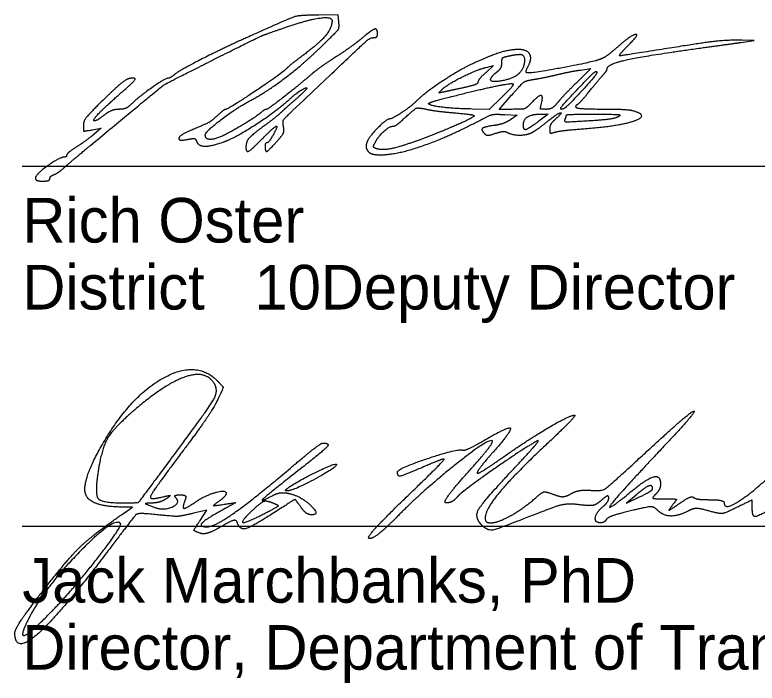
# Model space of a CAD drawing. Extents: x 0 to 34, y 0 to 22.
# Drawn here: x 24.977 to 27.305, y 5.404 to 7.5 of the extents above; entities that cross this region are included whole.
import ezdxf

# ---------------------------------------------------------------- set-up
doc = ezdxf.new("R2010")
doc.units = 0
doc.layers.add('SH_Data', color=7, linetype='Continuous')
doc.layers.add('SH_Text', color=7, linetype='Continuous')

msp = doc.modelspace()

# ---------------------------------------------------------------- linework, layer by layer
at = {"layer": 'SH_Data'}
for p, q in [((25, 7.0256), (28.5, 7.0256)), ((25, 5.8962), (28.5, 5.8962))]:
    msp.add_line(p, q, dxfattribs=at)
at = {"layer": 'SH_Text'}
for p, q in [((25.0414, 6.9885), (25.0414, 6.9885)), ((25.4623, 6.1012), (25.4623, 6.1012)), ((25.8276, 6.0114), (25.8276, 6.0114)), ((26.9766, 6.0134), (26.9766, 6.0134)), ((25.7828, 5.9697), (25.7828, 5.9697)), ((26.1995, 5.9824), (26.1995, 5.9824))]:
    msp.add_line(p, q, dxfattribs=at)
for points in [[(25.9926, 7.4778), (25.9902, 7.4996), (25.9302, 7.4989)], [(27.2539, 7.4131), (27.2952, 7.4189), (27.2575, 7.4199)], [(26.4552, 7.335), (26.4777, 7.3403), (26.4533, 7.318)], [(26.7502, 7.3265), (26.7828, 7.3312), (26.739, 7.2879)], [(26.5037, 7.2413), (26.4645, 7.2033), (26.4111, 7.2043)], [(26.5364, 7.2033), (26.4955, 7.2033), (26.5347, 7.2479)], [(26.513, 7.1869), (26.5522, 7.1846), (26.5308, 7.1706)], [(26.624, 7.1883), (26.6491, 7.1883), (26.6196, 7.166)], [(25.2195, 7.1391), (25.2477, 7.1441), (25.2252, 7.1252)], [(26.9248, 5.9937), (26.8953, 5.9681), (26.936, 5.9878)], [(25.3146, 5.9343), (25.3453, 5.9555), (25.3075, 5.9562)], [(25.5576, 5.9144), (25.5788, 5.9468), (25.5371, 5.9367)]]:
    msp.add_lwpolyline(points, dxfattribs=at)
for points in [[(25.9302, 7.4989), (25.8677, 7.4982), (25.8413, 7.49), (25.7052, 7.4288)], [(25.8327, 7.4628), (25.8967, 7.4847), (25.9714, 7.4947), (25.9714, 7.4814)], [(25.9714, 7.4814), (25.9714, 7.4575), (25.9264, 7.4061), (25.8672, 7.3626)], [(25.9326, 7.3953), (25.9866, 7.4476), (25.9948, 7.4589), (25.9926, 7.4778)], [(25.6227, 7.3706), (25.7348, 7.4269), (25.7605, 7.4382), (25.8327, 7.4628)], [(26.1139, 7.4396), (26.1139, 7.4576), (26.0963, 7.4527), (26.0646, 7.4259)], [(25.7052, 7.4288), (25.625, 7.3928), (25.4891, 7.3232), (25.4758, 7.3114)], [(25.8476, 7.1992), (26.069, 7.4088), (26.0909, 7.4283), (26.1045, 7.4283)], [(26.1045, 7.4283), (26.1097, 7.4283), (26.1139, 7.4334), (26.1139, 7.4396)], [(26.9007, 7.404), (26.9375, 7.4408), (26.908, 7.4355), (26.8651, 7.3975)], [(26.0646, 7.4259), (26.0484, 7.4122), (26.0115, 7.3857), (25.9827, 7.3671)], [(26.9974, 7.39), (26.8771, 7.3705), (26.8684, 7.3717), (26.9007, 7.404)], [(27.2575, 7.4199), (27.213, 7.421), (27.1291, 7.4114), (26.9974, 7.39)], [(27.1272, 7.3955), (27.1742, 7.402), (27.2312, 7.4099), (27.2539, 7.4131)], [(25.7093, 7.2274), (25.763, 7.2558), (25.8777, 7.342), (25.9326, 7.3953)], [(26.5565, 7.3908), (26.529, 7.3908), (26.4672, 7.3717), (26.4117, 7.346)], [(26.5866, 7.3386), (26.5994, 7.3625), (26.5831, 7.3908), (26.5565, 7.3908)], [(26.8651, 7.3975), (26.8459, 7.3806), (26.8234, 7.3642), (26.8152, 7.3612)], [(26.8339, 7.3305), (26.8339, 7.3449), (26.9565, 7.3721), (27.1272, 7.3955)], [(25.2139, 7.0904), (25.4385, 7.2764), (25.4481, 7.2829), (25.6227, 7.3706)], [(25.8672, 7.3626), (25.8523, 7.3516), (25.8342, 7.3367), (25.8269, 7.3295)], [(25.9827, 7.3671), (25.9538, 7.3485), (25.92, 7.3245), (25.9077, 7.3139)], [(26.5039, 7.3491), (26.5039, 7.3625), (26.5092, 7.3675), (26.5273, 7.3711)], [(26.5273, 7.3711), (26.5402, 7.3737), (26.5554, 7.3758), (26.5611, 7.3758)], [(26.5611, 7.3758), (26.5761, 7.3758), (26.5741, 7.3331), (26.5583, 7.3164)], [(26.8152, 7.3612), (26.7878, 7.3511), (26.5861, 7.3137), (26.5818, 7.3179)], [(26.4117, 7.346), (26.3697, 7.3265), (26.2612, 7.2542), (26.2355, 7.2285)], [(26.3164, 7.2656), (26.3308, 7.2805), (26.4259, 7.328), (26.4552, 7.335)], [(26.4903, 7.3219), (26.4978, 7.3273), (26.5039, 7.3395), (26.5039, 7.3491)], [(26.5818, 7.3179), (26.5796, 7.3202), (26.5817, 7.3295), (26.5866, 7.3386)], [(25.4758, 7.3114), (25.4693, 7.3056), (25.4607, 7.3008), (25.4567, 7.3008)], [(25.8269, 7.3295), (25.8121, 7.3146), (25.6453, 7.2033), (25.638, 7.2033)], [(25.9077, 7.3139), (25.863, 7.2755), (25.7703, 7.2033), (25.7656, 7.2033)], [(26.4533, 7.318), (26.4399, 7.3058), (26.4289, 7.2924), (26.4289, 7.2882)], [(26.5583, 7.3164), (26.5419, 7.2991), (26.4609, 7.2857), (26.4706, 7.3019)], [(26.4706, 7.3019), (26.474, 7.3075), (26.4828, 7.3165), (26.4903, 7.3219)], [(26.6046, 7.2973), (26.6214, 7.2999), (26.6537, 7.3065), (26.6764, 7.3119)], [(26.6764, 7.3119), (26.6991, 7.3174), (26.7323, 7.3239), (26.7502, 7.3265)], [(26.8009, 7.3213), (26.8044, 7.3179), (26.7805, 7.2889), (26.7279, 7.2325)], [(26.7763, 7.3028), (26.7879, 7.3149), (26.799, 7.3233), (26.8009, 7.3213)], [(26.7814, 7.2633), (26.7999, 7.286), (26.8193, 7.309), (26.8245, 7.3145)], [(26.8245, 7.3145), (26.8297, 7.3199), (26.8339, 7.3271), (26.8339, 7.3305)], [(25.3343, 7.2995), (25.3262, 7.2982), (25.2908, 7.2688), (25.2555, 7.2342)], [(25.3245, 7.2679), (25.3522, 7.2921), (25.3556, 7.303), (25.3343, 7.2995)], [(25.4567, 7.3008), (25.448, 7.3008), (25.3583, 7.237), (25.3392, 7.2172)], [(26.4289, 7.2882), (26.4289, 7.2841), (26.4095, 7.2765), (26.3858, 7.2714)], [(26.5347, 7.2479), (26.5671, 7.2847), (26.5793, 7.2933), (26.6046, 7.2973)], [(26.739, 7.2879), (26.7149, 7.264), (26.6876, 7.2352), (26.6783, 7.2239)], [(26.6918, 7.2033), (26.6839, 7.2033), (26.7053, 7.2285), (26.7763, 7.3028)], [(25.2245, 7.1677), (25.2208, 7.1714), (25.2677, 7.2184), (25.3245, 7.2679)], [(25.8364, 7.2336), (25.8508, 7.2463), (25.869, 7.2602), (25.8767, 7.2645)], [(25.8767, 7.2645), (25.8975, 7.2761), (25.8849, 7.2583), (25.8523, 7.2301)], [(26.3239, 7.258), (26.3071, 7.2544), (26.3063, 7.2552), (26.3164, 7.2656)], [(26.3858, 7.2714), (26.3621, 7.2663), (26.3342, 7.2602), (26.3239, 7.258)], [(26.3292, 7.239), (26.426, 7.2638), (26.5355, 7.2867), (26.5393, 7.2829)], [(26.5393, 7.2829), (26.5413, 7.2809), (26.5253, 7.2622), (26.5037, 7.2413)], [(26.6283, 7.2221), (26.6345, 7.2468), (26.6185, 7.2468), (26.595, 7.222)], [(26.742, 7.2196), (26.7451, 7.221), (26.7628, 7.2406), (26.7814, 7.2633)], [(25.2555, 7.2342), (25.2091, 7.1888), (25.1914, 7.1662), (25.1914, 7.1528)], [(25.3392, 7.2172), (25.3319, 7.2096), (25.3156, 7.2033), (25.3031, 7.2033)], [(25.5739, 7.1234), (25.5739, 7.1329), (25.6697, 7.2065), (25.7093, 7.2274)], [(25.6272, 7.0996), (25.6642, 7.1124), (25.7908, 7.1934), (25.8364, 7.2336)], [(25.8523, 7.2301), (25.8377, 7.2174), (25.8201, 7.2016), (25.8132, 7.1949)], [(26.2355, 7.2285), (26.2202, 7.2132), (26.1609, 7.1733), (26.1534, 7.1733)], [(26.2743, 7.2204), (26.2723, 7.2224), (26.297, 7.2308), (26.3292, 7.239)], [(26.4111, 7.2043), (26.3558, 7.2052), (26.2806, 7.2141), (26.2743, 7.2204)], [(26.595, 7.222), (26.5804, 7.2066), (26.5702, 7.2033), (26.5364, 7.2033)], [(26.6426, 7.2033), (26.6261, 7.2033), (26.6242, 7.2058), (26.6283, 7.2221)], [(26.6783, 7.2239), (26.6681, 7.2114), (26.6541, 7.2033), (26.6426, 7.2033)], [(26.7279, 7.2325), (26.7129, 7.2165), (26.6967, 7.2033), (26.6918, 7.2033)], [(26.7364, 7.2102), (26.7364, 7.214), (26.7389, 7.2182), (26.742, 7.2196)], [(25.3031, 7.2033), (25.2901, 7.2033), (25.2693, 7.1949), (25.2544, 7.1835)], [(25.638, 7.2033), (25.6354, 7.2033), (25.6242, 7.1949), (25.613, 7.1846)], [(25.7517, 7.1957), (25.7371, 7.1834), (25.6893, 7.1529), (25.6525, 7.1324)], [(25.7656, 7.2033), (25.7629, 7.2033), (25.7567, 7.1999), (25.7517, 7.1957)], [(25.8132, 7.1949), (25.8063, 7.1881), (25.7818, 7.1687), (25.7588, 7.1517)], [(25.8191, 7.1496), (25.8162, 7.1649), (25.8219, 7.1749), (25.8476, 7.1992)], [(26.1856, 7.1641), (26.2298, 7.2043), (26.2407, 7.2094), (26.2695, 7.2032)], [(26.2695, 7.2032), (26.285, 7.1999), (26.3258, 7.1948), (26.3602, 7.1919)], [(26.817, 7.2032), (26.7727, 7.2033), (26.7364, 7.2064), (26.7364, 7.2102)], [(26.7664, 7.143), (26.8777, 7.1516), (26.9663, 7.1847), (26.9148, 7.1985)], [(26.9148, 7.1985), (26.9054, 7.2011), (26.8614, 7.2032), (26.817, 7.2032)], [(25.2544, 7.1835), (25.2402, 7.1727), (25.2267, 7.1655), (25.2245, 7.1677)], [(25.613, 7.1846), (25.5938, 7.1668), (25.5794, 7.1588), (25.5233, 7.135)], [(26.1534, 7.1733), (26.1425, 7.1733), (26.0854, 7.1149), (26.0801, 7.0983)], [(26.4164, 7.1813), (26.407, 7.1732), (26.305, 7.1294), (26.2414, 7.106)], [(26.3602, 7.1919), (26.3946, 7.189), (26.4199, 7.1842), (26.4164, 7.1813)], [(26.4307, 7.1667), (26.4656, 7.1849), (26.4812, 7.1887), (26.513, 7.1869)], [(26.5308, 7.1706), (26.519, 7.1629), (26.4962, 7.1549), (26.4802, 7.1527)], [(26.5714, 7.1534), (26.5714, 7.1708), (26.5978, 7.1883), (26.624, 7.1883)], [(26.6449, 7.1639), (26.6775, 7.1903), (26.6968, 7.1948), (26.669, 7.1696)], [(26.7767, 7.1668), (26.7131, 7.1628), (26.6994, 7.1638), (26.7025, 7.172)], [(26.7025, 7.172), (26.7047, 7.1775), (26.7064, 7.1835), (26.7064, 7.1852)], [(26.7064, 7.1852), (26.7064, 7.1869), (26.7461, 7.1882), (26.7945, 7.1881)], [(26.8686, 7.1797), (26.8609, 7.1753), (26.8195, 7.1694), (26.7767, 7.1668)], [(26.7945, 7.1881), (26.8616, 7.1879), (26.8793, 7.1859), (26.8686, 7.1797)], [(25.1914, 7.1528), (25.1914, 7.1354), (25.1932, 7.1345), (25.2195, 7.1391)], [(25.7588, 7.1517), (25.7189, 7.1222), (25.7014, 7.1015), (25.7014, 7.0838)], [(25.7513, 7.1096), (25.7897, 7.1485), (25.8038, 7.1532), (25.7854, 7.1209)], [(25.7988, 7.1031), (25.8165, 7.1232), (25.8218, 7.1354), (25.8191, 7.1496)], [(26.1074, 7.1008), (26.1171, 7.1195), (26.1514, 7.1502), (26.1631, 7.1506)], [(26.1245, 7.0608), (26.1741, 7.0608), (26.3334, 7.1159), (26.4307, 7.1667)], [(26.1631, 7.1506), (26.1675, 7.1507), (26.1776, 7.1568), (26.1856, 7.1641)], [(26.4802, 7.1527), (26.4487, 7.1485), (26.4377, 7.1391), (26.4499, 7.1269)], [(26.6196, 7.166), (26.5876, 7.1418), (26.5714, 7.1376), (26.5714, 7.1534)], [(26.5977, 7.1302), (26.6059, 7.1344), (26.6272, 7.1496), (26.6449, 7.1639)], [(26.669, 7.1696), (26.6607, 7.1621), (26.6539, 7.1494), (26.6539, 7.1413)], [(25.2252, 7.1252), (25.2128, 7.1149), (25.1883, 7.0972), (25.1708, 7.0859)], [(25.5233, 7.135), (25.492, 7.1218), (25.4899, 7.1027), (25.5205, 7.1094)], [(25.6525, 7.1324), (25.6154, 7.1117), (25.5739, 7.1069), (25.5739, 7.1234)], [(26.4499, 7.1269), (26.4551, 7.1217), (26.4661, 7.122), (26.4843, 7.1281)], [(26.4843, 7.1281), (26.4991, 7.1329), (26.515, 7.1345), (26.5198, 7.1316)], [(26.5198, 7.1316), (26.5338, 7.1229), (26.5815, 7.1221), (26.5977, 7.1302)], [(26.6539, 7.1413), (26.6539, 7.1295), (26.6573, 7.1276), (26.6708, 7.1318)], [(26.6708, 7.1318), (26.6801, 7.1346), (26.7231, 7.1397), (26.7664, 7.143)], [(25.5205, 7.1094), (25.5361, 7.1128), (25.5432, 7.1109), (25.5465, 7.1025)], [(25.5465, 7.1025), (25.5519, 7.0884), (25.5906, 7.087), (25.6272, 7.0996)], [(25.7014, 7.0838), (25.7014, 7.0677), (25.7189, 7.0767), (25.7513, 7.1096)], [(25.7614, 7.0871), (25.7614, 7.0689), (25.7732, 7.074), (25.7988, 7.1031)], [(25.7854, 7.1209), (25.7784, 7.1085), (25.7701, 7.0984), (25.767, 7.0984)], [(26.1083, 7.0807), (26.1012, 7.0836), (26.101, 7.0884), (26.1074, 7.1008)], [(26.2414, 7.106), (26.1841, 7.085), (26.1251, 7.0738), (26.1083, 7.0807)], [(25.1314, 7.0206), (25.1417, 7.0299), (25.1788, 7.0613), (25.2139, 7.0904)], [(25.1708, 7.0859), (25.1532, 7.0746), (25.1389, 7.0626), (25.1389, 7.0593)], [(25.767, 7.0984), (25.7639, 7.0984), (25.7614, 7.0933), (25.7614, 7.0871)], [(26.0801, 7.0983), (26.0774, 7.0896), (26.0792, 7.0777), (26.0842, 7.0717)], [(25.1389, 7.0593), (25.1389, 7.056), (25.1355, 7.0533), (25.1313, 7.0533)], [(26.0842, 7.0717), (26.0895, 7.0654), (26.1063, 7.0608), (26.1245, 7.0608)], [(25.1313, 7.0533), (25.1171, 7.0533), (25.0414, 6.9988), (25.0414, 6.9885)], [(25.0995, 6.9987), (25.1067, 7.0014), (25.1211, 7.0112), (25.1314, 7.0206)], [(25.0414, 6.9885), (25.0414, 6.9822), (25.0499, 6.9783), (25.0639, 6.9783)], [(25.0639, 6.9783), (25.0763, 6.9783), (25.0864, 6.9818), (25.0864, 6.9861)], [(25.0864, 6.9861), (25.0864, 6.9903), (25.0923, 6.996), (25.0995, 6.9987)], [(25.251, 6.152), (25.3372, 6.3024), (25.5454, 6.4184), (25.611, 6.3527)], [(25.6021, 6.3436), (25.5761, 6.3856), (25.45, 6.3444), (25.3547, 6.2628)], [(25.4623, 6.1012), (25.5837, 6.2647), (25.6161, 6.3209), (25.6021, 6.3436)], [(25.611, 6.3527), (25.6298, 6.334), (25.6298, 6.3289), (25.6115, 6.2905)], [(25.6115, 6.2905), (25.6006, 6.2675), (25.5488, 6.192), (25.4966, 6.1226)], [(25.3547, 6.2628), (25.288, 6.2058), (25.2492, 6.1416), (25.2381, 6.0704)], [(26.5047, 6.1105), (26.5853, 6.1671), (26.7166, 6.2443), (26.7323, 6.2443)], [(26.7323, 6.2443), (26.7372, 6.2443), (26.6959, 6.2017), (26.6405, 6.1496)], [(26.959, 6.1309), (27.034, 6.2), (27.1, 6.2566), (27.1058, 6.2567)], [(27.1058, 6.2567), (27.1115, 6.2568), (27.0595, 6.1966), (26.9901, 6.123)], [(26.4458, 6.164), (26.5245, 6.2101), (26.5368, 6.1969), (26.4775, 6.1296)], [(25.3075, 5.9562), (25.2096, 5.9579), (25.1862, 6.039), (25.251, 6.152)], [(25.8411, 6.0785), (25.8916, 6.1214), (25.9371, 6.1565), (25.9422, 6.1566)], [(25.9422, 6.1566), (25.9671, 6.1571), (25.9437, 6.1316), (25.8578, 6.0643)], [(26.4738, 6.1637), (26.4642, 6.1734), (26.2545, 6.0064), (26.1766, 5.9271)], [(26.6141, 6.1633), (26.565, 6.1355), (26.3767, 6.0033), (26.3635, 5.9873)], [(26.3801, 6.1348), (26.3857, 6.1329), (26.4152, 6.1461), (26.4458, 6.164)], [(26.396, 6.0634), (26.4423, 6.1151), (26.4773, 6.1603), (26.4738, 6.1637)], [(26.6405, 6.1496), (26.5409, 6.0559), (26.4516, 5.9477), (26.4516, 5.9208)], [(26.5489, 6.0844), (26.5951, 6.1336), (26.6244, 6.1691), (26.6141, 6.1633)], [(26.1768, 6.0662), (26.177, 6.0767), (26.3644, 6.1399), (26.3801, 6.1348)], [(26.4775, 6.1296), (26.4495, 6.0978), (26.4266, 6.0681), (26.4266, 6.0637)], [(26.784, 6.0085), (26.8175, 6.0057), (26.8409, 6.0221), (26.959, 6.1309)], [(26.9901, 6.123), (26.8606, 5.9855), (26.8285, 5.9382), (26.9107, 6.0059)], [(25.3162, 5.9693), (25.3628, 5.9693), (25.3674, 5.9734), (25.4623, 6.1012)], [(25.4966, 6.1226), (25.4443, 6.0532), (25.4016, 5.9926), (25.4016, 5.9878)], [(26.1995, 5.9824), (26.2705, 6.0508), (26.3258, 6.1068), (26.3224, 6.1068)], [(26.3224, 6.1068), (26.319, 6.1068), (26.2899, 6.0956), (26.2578, 6.0818)], [(26.4266, 6.0637), (26.4266, 6.0592), (26.4617, 6.0803), (26.5047, 6.1105)], [(25.5797, 5.8943), (25.6028, 5.8943), (25.7289, 5.9831), (25.8411, 6.0785)], [(25.8276, 6.0114), (25.848, 6.0292), (25.9801, 6.095), (25.9852, 6.0899)], [(25.9852, 6.0899), (25.9914, 6.0837), (25.8488, 6.0068), (25.8311, 6.0068)], [(26.2578, 6.0818), (26.1952, 6.055), (26.1765, 6.0514), (26.1768, 6.0662)], [(26.4418, 5.8987), (26.4166, 5.9239), (26.4455, 5.974), (26.5489, 6.0844)], [(25.2381, 6.0704), (25.2267, 5.997), (25.2481, 5.9693), (25.3162, 5.9693)], [(25.8578, 6.0643), (25.7646, 5.9913), (25.7432, 5.9697), (25.7871, 5.9932)], [(26.3302, 5.9693), (26.3199, 5.9693), (26.3488, 6.0106), (26.396, 6.0634)], [(27.2016, 5.9678), (27.2016, 5.945), (27.2969, 6.0064), (27.3672, 6.0746)], [(26.9107, 6.0059), (26.9591, 6.0458), (27.0016, 6.0562), (27.0016, 6.0281)], [(25.8311, 6.0068), (25.8263, 6.0068), (25.8248, 6.0089), (25.8276, 6.0114)], [(26.721, 5.998), (26.7344, 6.0056), (26.7627, 6.0103), (26.784, 6.0085)], [(26.9766, 6.0134), (26.9766, 6.0269), (26.9525, 6.0177), (26.9248, 5.9937)], [(26.936, 5.9878), (26.9583, 5.9986), (26.9766, 6.0101), (26.9766, 6.0134)], [(27.0016, 6.0281), (27.0016, 6.0191), (26.9948, 6.0051), (26.9866, 5.9968)], [(25.4016, 5.9878), (25.4016, 5.983), (25.4171, 5.9827), (25.436, 5.9871)], [(25.412, 5.9561), (25.4419, 5.9441), (25.4981, 5.9686), (25.4807, 5.9861)], [(25.436, 5.9871), (25.4615, 5.993), (25.4655, 5.9918), (25.4516, 5.9824)], [(25.4807, 5.9861), (25.4761, 5.9906), (25.4824, 5.9943), (25.4946, 5.9943)], [(25.4946, 5.9943), (25.5092, 5.9943), (25.5143, 5.9879), (25.5096, 5.9756)], [(25.5457, 5.9737), (25.5746, 5.9935), (25.6391, 6.011), (25.6391, 5.9991)], [(25.6391, 5.9991), (25.6391, 5.9945), (25.6294, 5.9837), (25.6175, 5.975)], [(25.7871, 5.9932), (25.7997, 6), (25.8236, 6.0021), (25.8402, 5.9979)], [(25.8402, 5.9979), (25.8763, 5.9888), (25.9347, 5.9318), (25.908, 5.9318)], [(26.3635, 5.9873), (26.3553, 5.9774), (26.3403, 5.9693), (26.3302, 5.9693)], [(26.4696, 5.9068), (26.4914, 5.9068), (26.5727, 5.952), (26.6091, 5.9843)], [(26.6091, 5.9843), (26.6294, 6.0024), (26.6423, 6.005), (26.666, 5.996)], [(26.666, 5.996), (26.6862, 5.9883), (26.705, 5.989), (26.721, 5.998)], [(26.8391, 5.9853), (26.8391, 5.9924), (26.8289, 5.989), (26.8165, 5.9778)], [(26.8203, 5.9568), (26.8307, 5.9654), (26.8391, 5.9782), (26.8391, 5.9853)], [(26.9866, 5.9968), (26.9749, 5.9852), (26.9808, 5.9818), (27.0131, 5.9818)], [(27.0592, 5.9663), (27.0807, 5.9813), (27.1014, 5.9904), (27.1053, 5.9865)], [(27.1053, 5.9865), (27.1092, 5.9825), (27.1325, 5.9793), (27.157, 5.9793)], [(25.4078, 5.9687), (25.3854, 5.9678), (25.3859, 5.9665), (25.412, 5.9561)], [(25.4516, 5.9824), (25.4413, 5.9754), (25.4216, 5.9693), (25.4078, 5.9687)], [(25.5096, 5.9756), (25.5006, 5.9523), (25.5135, 5.9517), (25.5457, 5.9737)], [(25.6175, 5.975), (25.5986, 5.9612), (25.6005, 5.9599), (25.6331, 5.9648)], [(25.6331, 5.9648), (25.6699, 5.9704), (25.6697, 5.9701), (25.6243, 5.945)], [(25.7828, 5.9697), (25.7656, 5.9761), (25.7491, 5.9709), (25.7297, 5.9532)], [(25.7547, 5.9334), (25.8011, 5.9571), (25.8047, 5.9617), (25.7828, 5.9697)], [(25.8732, 5.9565), (25.8564, 5.9806), (25.8543, 5.9801), (25.7886, 5.9377)], [(26.0891, 5.8575), (26.0788, 5.8577), (26.1284, 5.9139), (26.1995, 5.9824)], [(26.747, 5.9634), (26.7178, 5.9671), (26.678, 5.9606), (26.6415, 5.9462)], [(26.8165, 5.9778), (26.8008, 5.9636), (26.7796, 5.9592), (26.747, 5.9634)], [(27.0131, 5.9818), (27.0507, 5.9818), (27.053, 5.9798), (27.0375, 5.9604)], [(27.0375, 5.9604), (27.0255, 5.9454), (27.032, 5.9472), (27.0592, 5.9663)], [(27.157, 5.9793), (27.1815, 5.9793), (27.2016, 5.9741), (27.2016, 5.9678)], [(27.2891, 5.9553), (27.2891, 5.9782), (27.288, 5.9782), (27.2419, 5.9553)], [(25.5371, 5.9367), (25.4967, 5.927), (25.4744, 5.9266), (25.3959, 5.9344)], [(25.6243, 5.945), (25.5732, 5.9168), (25.5535, 5.8943), (25.5797, 5.8943)], [(25.7886, 5.9377), (25.7197, 5.8934), (25.6822, 5.8836), (25.6741, 5.908)], [(25.7297, 5.9532), (25.6855, 5.9127), (25.6967, 5.9038), (25.7547, 5.9334)], [(25.908, 5.9318), (25.8984, 5.9318), (25.8827, 5.9429), (25.8732, 5.9565)], [(26.6415, 5.9462), (26.4954, 5.8885), (26.4604, 5.8802), (26.4418, 5.8987)], [(26.8134, 5.9068), (26.795, 5.9068), (26.7995, 5.9396), (26.8203, 5.9568)], [(26.9077, 5.9443), (26.8693, 5.9351), (26.835, 5.9229), (26.8315, 5.9172)], [(26.992, 5.9464), (26.9809, 5.9575), (26.9608, 5.957), (26.9077, 5.9443)], [(27.0883, 5.9439), (27.0576, 5.9275), (27.0097, 5.9287), (26.992, 5.9464)], [(27.1528, 5.944), (27.1259, 5.9517), (27.1028, 5.9517), (27.0883, 5.9439)], [(27.2419, 5.9553), (27.2045, 5.9368), (27.1859, 5.9345), (27.1528, 5.944)], [(27.351, 5.9522), (27.306, 5.9256), (27.2891, 5.9265), (27.2891, 5.9553)], [(25.0637, 5.6921), (25.1414, 5.7926), (25.2214, 5.8699), (25.3146, 5.9343)], [(25.3959, 5.9344), (25.3625, 5.9377), (25.3507, 5.9272), (25.2741, 5.8256)], [(25.5564, 5.8744), (25.5382, 5.8814), (25.5383, 5.885), (25.5576, 5.9144)], [(25.6741, 5.908), (25.6713, 5.9166), (25.652, 5.9114), (25.623, 5.8942)], [(26.1766, 5.9271), (26.1388, 5.8887), (26.0994, 5.8573), (26.0891, 5.8575)], [(26.4516, 5.9208), (26.4516, 5.9131), (26.4597, 5.9068), (26.4696, 5.9068)], [(26.8315, 5.9172), (26.828, 5.9115), (26.8198, 5.9068), (26.8134, 5.9068)], [(25.3075, 5.9051), (25.2866, 5.926), (25.0681, 5.7003), (25.0218, 5.61)], [(25.0919, 5.6287), (25.1595, 5.6978), (25.3152, 5.8974), (25.3075, 5.9051)], [(25.623, 5.8942), (25.5973, 5.8791), (25.5674, 5.8702), (25.5564, 5.8744)], [(25.2741, 5.8256), (25.1217, 5.6235), (24.9766, 5.4948), (24.9766, 5.5618)], [(24.9766, 5.5618), (24.9766, 5.5715), (25.0158, 5.6301), (25.0637, 5.6921)], [(25.0218, 5.61), (24.9905, 5.549), (25.0222, 5.5575), (25.0919, 5.6287)]]:
    msp.add_open_spline(points, degree=2, dxfattribs=at)

# ---------------------------------------------------------------- texts
for s, p in [('Rich Oster', (25, 6.7856)), ('District       Deputy Director', (25, 6.5756)), ('              10', (25, 6.5756)), ('Jack Marchbanks, PhD', (25, 5.6562)), ('Director, Department of Transportation', (25, 5.4462))]:
    msp.add_text(s, height=0.14, dxfattribs=at).set_placement(p)

doc.saveas('drawing.dxf')
